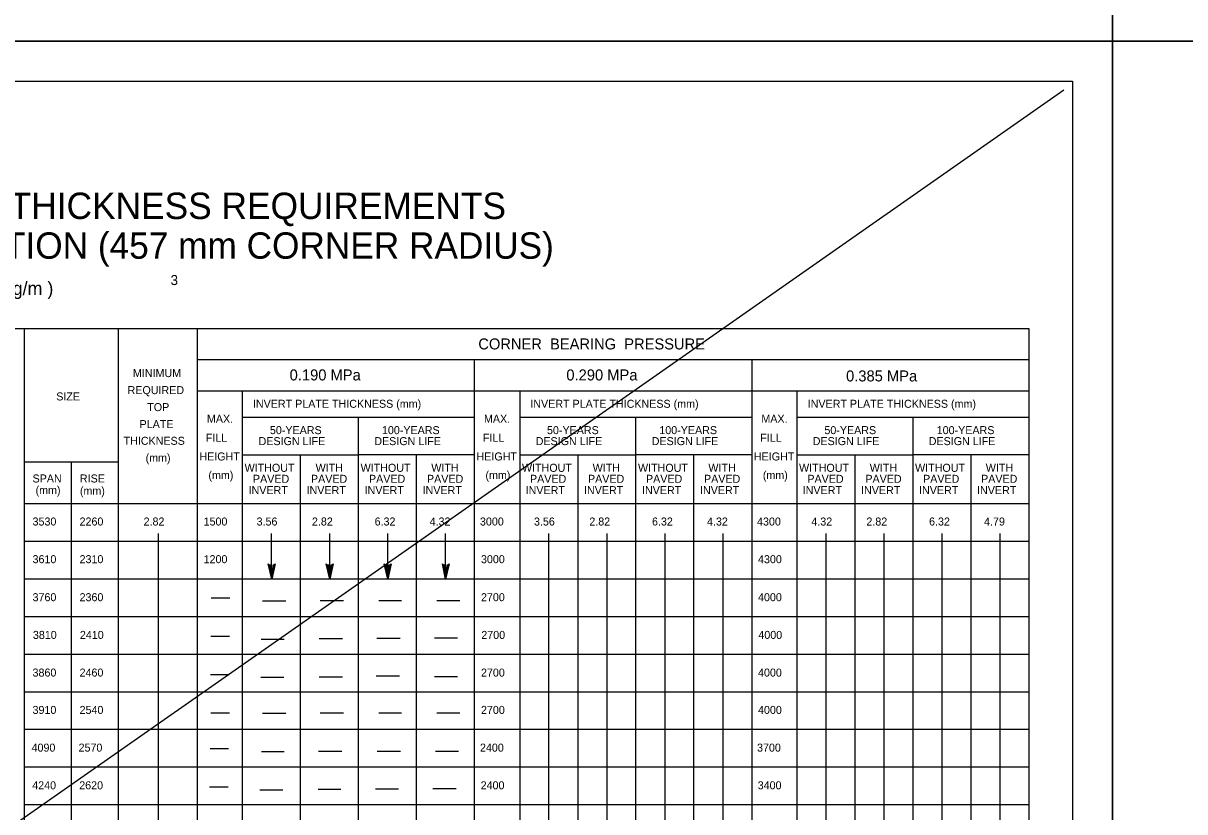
# Model space of a CAD drawing. Extents: x 591 to 2288, y -189 to 2187.
# Drawn here: x 1024 to 1459.5, y 1304.4 to 1600 of the extents above; entities that cross this region are included whole.
import ezdxf

# ---------------------------------------------------------------- set-up
doc = ezdxf.new("R2010")
doc.units = 0
for name, color, linetype in [('1', 7, 'Continuous'), ('2', 7, 'Continuous'), ('PLT-BNDY', 7, 'Continuous')]:
    doc.layers.add(name, color=color, linetype=linetype)

msp = doc.modelspace()

# ---------------------------------------------------------------- linework, layer by layer
at = {"layer": '1'}
msp.add_line((1414.15, 1574.88), (614.04, 1015.14), dxfattribs=at)
at = {"layer": '2'}
for p, q in [((631.34, 1578.21), (1417.34, 1578.21)), ((1417.34, 1578.21), (1417.34, 1014.21)), ((646.96, 1485.59), (1400.96, 1485.59)), ((1024.34, 1485.59), (1024.34, 1181.59)), ((1059.59, 1485.59), (1059.59, 1181.59)), ((1089.21, 1485.59), (1089.21, 1181.59)), ((1400.96, 1485.59), (1400.96, 1181.59)), ((1400.96, 1473.84), (1089.21, 1473.84)), ((1193.09, 1473.84), (1193.09, 1181.59)), ((1297.09, 1473.84), (1297.09, 1181.59)), ((1089.21, 1462.21), (1193.09, 1462.21)), ((1106.09, 1462.21), (1106.09, 1181.59)), ((1193.09, 1462.21), (1297.09, 1462.21)), ((1210.09, 1462.21), (1210.09, 1181.59)), ((1297.09, 1462.21), (1400.96, 1462.21)), ((1313.96, 1462.21), (1313.96, 1181.59)), ((1106.09, 1452.34), (1193.09, 1452.34)), ((1149.59, 1452.34), (1149.59, 1181.59)), ((1210.09, 1452.34), (1297.09, 1452.34)), ((1253.46, 1452.34), (1253.46, 1181.59)), ((1313.96, 1452.34), (1400.96, 1452.34)), ((1357.46, 1452.34), (1357.46, 1181.59)), ((1106.09, 1438.21), (1149.59, 1438.21)), ((1127.84, 1438.21), (1127.84, 1181.59)), ((1193.09, 1438.21), (1149.59, 1438.21)), ((1171.34, 1438.21), (1171.34, 1181.59)), ((1210.09, 1438.21), (1253.46, 1438.21)), ((1231.84, 1438.21), (1231.84, 1181.59)), ((1297.09, 1438.21), (1253.46, 1438.21)), ((1275.21, 1438.21), (1275.21, 1181.59)), ((1313.96, 1438.21), (1357.46, 1438.21)), ((1335.71, 1438.21), (1335.71, 1181.59)), ((1400.96, 1438.21), (1357.46, 1438.21)), ((1379.21, 1438.21), (1379.21, 1181.59)), ((1059.59, 1435.46), (1024.34, 1435.46)), ((1041.96, 1435.46), (1041.96, 1181.59)), ((1400.96, 1419.84), (1024.34, 1419.84)), ((1074.59, 1408.71), (1074.59, 1181.59)), ((1116.96, 1408.71), (1116.96, 1391.71)), ((1138.84, 1408.71), (1138.84, 1391.71)), ((1160.59, 1408.71), (1160.59, 1391.71)), ((1182.21, 1408.71), (1182.21, 1391.71)), ((1220.84, 1408.71), (1220.84, 1181.59)), ((1242.71, 1408.71), (1242.71, 1181.59)), ((1264.46, 1408.71), (1264.46, 1181.59)), ((1286.21, 1408.71), (1286.21, 1181.59)), ((1324.84, 1408.71), (1324.84, 1181.59)), ((1346.59, 1408.71), (1346.59, 1181.59)), ((1368.34, 1408.71), (1368.34, 1181.59)), ((1390.09, 1408.71), (1390.09, 1181.59)), ((1024.34, 1405.84), (1400.96, 1405.84)), ((1024.34, 1391.71), (1400.96, 1391.71)), ((1094.46, 1384.59), (1101.46, 1384.59)), ((1113.71, 1383.46), (1122.46, 1383.46)), ((1135.34, 1383.59), (1144.09, 1383.59)), ((1157.34, 1383.59), (1165.84, 1383.59)), ((1179.09, 1383.59), (1187.71, 1383.59)), ((1024.34, 1377.59), (1400.96, 1377.59)), ((1094.34, 1370.21), (1101.34, 1370.21)), ((1113.21, 1369.09), (1121.84, 1369.09)), ((1134.96, 1369.34), (1143.71, 1369.34)), ((1156.59, 1369.46), (1165.34, 1369.46)), ((1178.21, 1369.59), (1186.84, 1369.59)), ((1024.34, 1363.46), (1400.96, 1363.46)), ((1094.21, 1355.84), (1101.21, 1355.84)), ((1113.09, 1354.84), (1121.71, 1354.84)), ((1134.96, 1354.96), (1143.71, 1354.96)), ((1156.34, 1355.34), (1165.09, 1355.34)), ((1178.21, 1355.09), (1186.84, 1355.09)), ((1024.34, 1349.34), (1400.96, 1349.34)), ((1094.34, 1341.46), (1101.34, 1341.46)), ((1113.71, 1341.34), (1122.46, 1341.34)), ((1135.34, 1341.46), (1144.09, 1341.46)), ((1157.34, 1341.46), (1165.84, 1341.46)), ((1179.09, 1341.46), (1187.71, 1341.46)), ((1024.34, 1335.34), (1400.96, 1335.34)), ((1094.09, 1328.09), (1100.96, 1328.09)), ((1113.34, 1326.96), (1121.84, 1326.96)), ((1134.71, 1327.09), (1143.46, 1327.09)), ((1156.71, 1327.09), (1165.46, 1327.09)), ((1178.59, 1327.09), (1187.21, 1327.09)), ((1024.34, 1321.21), (1400.96, 1321.21)), ((1093.84, 1313.71), (1100.84, 1313.71)), ((1112.71, 1312.59), (1121.34, 1312.59)), ((1134.59, 1312.84), (1143.09, 1312.84)), ((1156.09, 1312.96), (1164.71, 1312.96)), ((1177.59, 1313.09), (1186.34, 1313.09)), ((1024.34, 1307.09), (1400.96, 1307.09))]:
    msp.add_line(p, q, dxfattribs=at)
for points in [[(1118.09, 1396.96), (1117.59, 1396.84), (1117.21, 1391.59), (1118.09, 1396.96), (1118.46, 1397.34), (1117.21, 1391.59), (1116.84, 1396.84), (1116.21, 1396.96), (1117.21, 1391.59), (1115.84, 1397.34), (1116.21, 1396.96)], [(1139.84, 1396.96), (1139.34, 1396.84), (1138.96, 1391.59), (1139.84, 1396.96), (1140.21, 1397.34), (1138.96, 1391.59), (1138.59, 1396.84), (1137.96, 1396.96), (1138.96, 1391.59), (1137.59, 1397.34), (1137.96, 1396.96)], [(1161.59, 1396.96), (1161.09, 1396.84), (1160.71, 1391.59), (1161.59, 1396.96), (1161.96, 1397.34), (1160.71, 1391.59), (1160.34, 1396.84), (1159.71, 1396.96), (1160.71, 1391.59), (1159.34, 1397.34), (1159.71, 1396.96)], [(1183.34, 1396.96), (1182.84, 1396.84), (1182.34, 1391.59), (1183.34, 1396.96), (1183.71, 1397.34), (1182.34, 1391.59), (1182.09, 1396.84), (1181.59, 1396.96), (1182.34, 1391.59), (1181.21, 1397.34), (1181.59, 1396.96)]]:
    msp.add_lwpolyline(points, dxfattribs=at)
at = {"layer": 'PLT-BNDY'}
for points in [[(591.34, 2187.21), (1432.34, 2187.21), (1432.34, 1593.21), (591.34, 1593.21)], [(1432.34, 2187.21), (2273.34, 2187.21), (2273.34, 1593.21), (1432.34, 1593.21)], [(591.34, 1593.21), (1432.34, 1593.21), (1432.34, 999.21), (591.34, 999.21)], [(1432.34, 1593.21), (2273.34, 1593.21), (2273.34, 999.21), (1432.34, 999.21)]]:
    msp.add_lwpolyline(points, close=True, dxfattribs=at)

# ---------------------------------------------------------------- texts
at = {"layer": '2'}
for s, height, p in [('STEEL STRUCTURAL PLATE PIPE-ARCH THICKNESS REQUIREMENTS', 9.8993, (759.21, 1526.59)), ('WITH MINIMUM  PREDICTED METAL LOSS CONDITION (457 mm CORNER RADIUS)', 9.8752, (703.46, 1511.71)), ('(BACKFILL UNIT DENSITY = 2250 kg/m )', 5.0003, (910.21, 1498.09)), ('3', 3.75, (1079.21, 1501.84)), ('CORNER  BEARING  PRESSURE', 4.1138, (1194.59, 1477.71)), ('MINIMUM', 3, (1065.09, 1467.34)), ('0.190 MPa', 4.125, (1123.84, 1466.09)), ('0.290 MPa', 4.125, (1227.59, 1466.09)), ('0.385 MPa', 4.125, (1332.46, 1465.71)), ('REQUIRED', 3, (1063.09, 1460.96)), ('SIZE', 3, (1036.34, 1458.59)), ('INVERT PLATE THICKNESS (mm)', 3, (1110.09, 1455.84)), ('INVERT PLATE THICKNESS (mm)', 3, (1214.09, 1455.84)), ('INVERT PLATE THICKNESS (mm)', 3, (1318.09, 1455.84)), ('TOP', 3, (1070.46, 1454.59)), ('PLATE', 3, (1067.59, 1448.21)), ('MAX.', 3, (1092.84, 1450.22)), ('MAX.', 3, (1196.71, 1450.22)), ('MAX.', 3, (1300.71, 1450.22)), ('FILL', 3, (1092.42, 1443.09)), ('50-YEARS', 3, (1116.46, 1445.96)), ('100-YEARS', 3, (1158.46, 1445.96)), ('FILL', 3, (1196.29, 1443.09)), ('50-YEARS', 3, (1220.34, 1445.96)), ('100-YEARS', 3, (1262.46, 1445.96)), ('FILL', 3, (1300.29, 1443.09)), ('50-YEARS', 3, (1324.34, 1445.96)), ('100-YEARS', 3, (1366.46, 1445.96)), ('THICKNESS', 3, (1061.59, 1441.96)), ('DESIGN LIFE', 3, (1112.21, 1441.84)), ('DESIGN LIFE', 3, (1155.59, 1441.84)), ('DESIGN LIFE', 3, (1216.09, 1441.84)), ('DESIGN LIFE', 3, (1259.59, 1441.84)), ('DESIGN LIFE', 3, (1319.96, 1441.84)), ('DESIGN LIFE', 3, (1363.46, 1441.84)), ('(mm)', 3, (1069.84, 1435.59)), ('HEIGHT', 3, (1090.02, 1436.09)), ('HEIGHT', 3, (1193.9, 1436.09)), ('HEIGHT', 3, (1297.9, 1436.09)), ('WITHOUT', 3, (1106.96, 1431.84)), ('WITH', 3, (1133.59, 1431.84)), ('WITHOUT', 3, (1150.46, 1431.84)), ('WITH', 3, (1176.96, 1431.84)), ('WITHOUT', 3, (1210.96, 1431.84)), ('WITH', 3, (1237.46, 1431.84)), ('WITHOUT', 3, (1254.46, 1431.84)), ('WITH', 3, (1280.84, 1431.84)), ('WITHOUT', 3, (1314.84, 1431.84)), ('WITH', 3, (1341.34, 1431.84)), ('WITHOUT', 3, (1358.34, 1431.84)), ('WITH', 3, (1384.84, 1431.84)), ('SPAN', 3, (1027.46, 1427.84)), ('RISE', 3, (1045.21, 1427.84)), ('(mm)', 3, (1093.39, 1429.09)), ('PAVED', 3, (1110.09, 1427.71)), ('PAVED', 3, (1131.84, 1427.71)), ('PAVED', 3, (1153.59, 1427.71)), ('PAVED', 3, (1175.34, 1427.71)), ('(mm)', 3, (1197.26, 1429.09)), ('PAVED', 3, (1213.96, 1427.71)), ('PAVED', 3, (1235.71, 1427.71)), ('PAVED', 3, (1257.46, 1427.71)), ('PAVED', 3, (1279.21, 1427.71)), ('(mm)', 3, (1301.26, 1429.09)), ('PAVED', 3, (1317.96, 1427.71)), ('PAVED', 3, (1339.71, 1427.71)), ('PAVED', 3, (1361.34, 1427.71)), ('PAVED', 3, (1383.09, 1427.71)), ('(mm)', 3, (1028.59, 1423.46)), ('(mm)', 3, (1045.21, 1423.21)), ('INVERT', 3, (1108.46, 1423.46)), ('INVERT', 3, (1130.21, 1423.46)), ('INVERT', 3, (1151.96, 1423.46)), ('INVERT', 3, (1173.71, 1423.46)), ('INVERT', 3, (1212.34, 1423.46)), ('INVERT', 3, (1234.21, 1423.46)), ('INVERT', 3, (1255.96, 1423.46)), ('INVERT', 3, (1277.71, 1423.46)), ('INVERT', 3, (1316.21, 1423.46)), ('INVERT', 3, (1338.09, 1423.46)), ('INVERT', 3, (1359.84, 1423.46)), ('INVERT', 3, (1381.59, 1423.46)), ('3530', 3, (1027.46, 1411.71)), ('2260', 3, (1045.09, 1411.71)), ('2.82', 3, (1069.09, 1411.71)), ('1500', 3, (1091.59, 1411.71)), ('3.56', 3, (1111.46, 1411.71)), ('2.82', 3, (1132.21, 1411.71)), ('6.32', 3, (1155.71, 1411.71)), ('4.32', 3, (1176.34, 1411.71)), ('3000', 3, (1195.21, 1411.71)), ('3.56', 3, (1215.46, 1411.71)), ('2.82', 3, (1236.21, 1411.71)), ('6.32', 3, (1259.71, 1411.71)), ('4.32', 3, (1280.34, 1411.71)), ('4300', 3, (1299.09, 1411.71)), ('4.32', 3, (1319.46, 1411.71)), ('2.82', 3, (1340.09, 1411.71)), ('6.32', 3, (1363.59, 1411.71)), ('4.79', 3, (1384.21, 1411.71)), ('3610', 3, (1027.46, 1397.59)), ('2310', 3, (1045.09, 1397.59)), ('1200', 3, (1091.59, 1397.59)), ('3000', 3, (1195.59, 1397.59)), ('4300', 3, (1299.46, 1397.59)), ('3760', 3, (1027.46, 1383.34)), ('2360', 3, (1045.09, 1383.34)), ('2700', 3, (1195.59, 1383.34)), ('4000', 3, (1299.46, 1383.34)), ('3810', 3, (1027.59, 1369.21)), ('2410', 3, (1045.21, 1369.21)), ('2700', 3, (1195.71, 1369.21)), ('4000', 3, (1299.59, 1369.21)), ('3860', 3, (1027.46, 1355.09)), ('2460', 3, (1045.09, 1355.09)), ('2700', 3, (1195.59, 1355.09)), ('4000', 3, (1299.46, 1355.09)), ('3910', 3, (1027.46, 1341.09)), ('2540', 3, (1045.09, 1341.09)), ('2700', 3, (1195.59, 1341.09)), ('4000', 3, (1299.46, 1341.09)), ('4090', 3, (1027.09, 1326.96)), ('2570', 3, (1044.71, 1326.96)), ('2400', 3, (1195.21, 1326.96)), ('3700', 3, (1299.09, 1326.96)), ('4240', 3, (1027.34, 1312.84)), ('2620', 3, (1044.96, 1312.84)), ('2400', 3, (1195.46, 1312.84)), ('3400', 3, (1299.34, 1312.84))]:
    msp.add_text(s, height=height, dxfattribs=at).set_placement(p)

doc.saveas('drawing.dxf')
